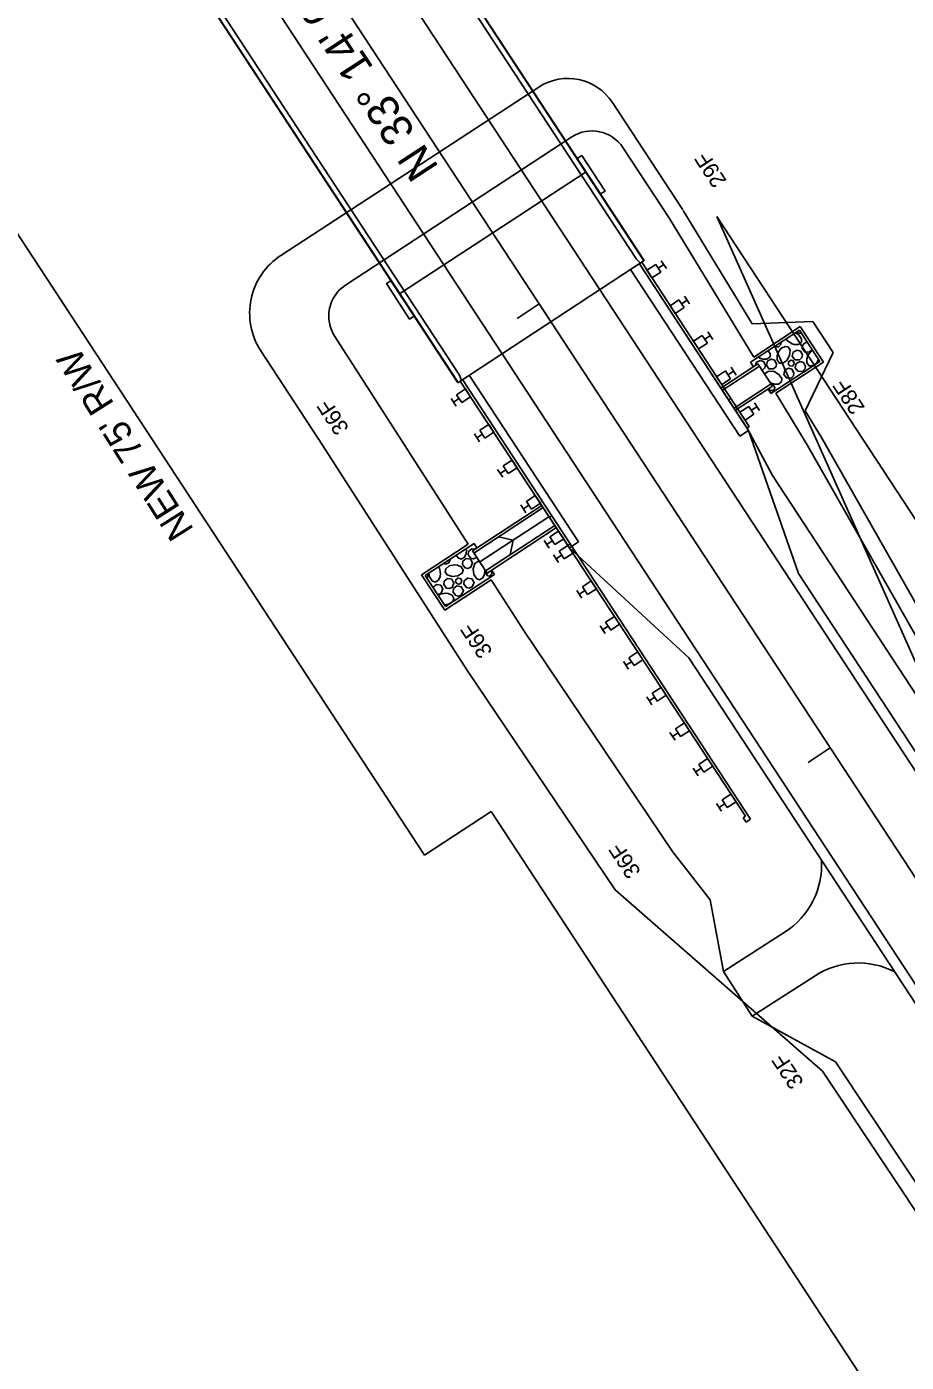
# Model space of a CAD drawing. Extents: x 1551641 to 1624343, y 1119533 to 1136600.
# Drawn here: x 1552572.7 to 1552738.3, y 1134049.4 to 1134301 of the extents above; entities that cross this region are included whole.
import ezdxf

# ---------------------------------------------------------------- set-up
doc = ezdxf.new("R2010")
doc.units = 0
for name, color, linetype in [('Prop CMT Approach Slab', 7, 'Continuous'), ('Prop CMT Concrete Structures', 7, 'Continuous'), ('Prop CMT Guardrail Graphics', 7, 'Continuous'), ('Prop CMT Pvmt Concrete', 7, 'Continuous'), ('Prop CMT Pvmt Surface Shoulder', 7, 'Continuous'), ('RD_HC_Data', 7, 'Continuous'), ('RD_HC_Data_Tic', 7, 'Continuous'), ('RD_Sketch1', 7, 'Continuous'), ('RD_XS_Base', 7, 'Continuous'), ('RD_XS_EarthShd', 7, 'Continuous'), ('RD_XS_ExGround', 7, 'Continuous'), ('RD_XS_ExPaveRet', 7, 'Continuous'), ('RD_XS_Pave', 7, 'Continuous'), ('RD_XS_PaveShd', 7, 'Continuous'), ('RD_XS_TieSlope', 7, 'Continuous'), ('RD_XS_TX_Elev_EX', 7, 'Continuous'), ('RD_XS_TX_Slope', 7, 'Continuous'), ('Scratch_Level_0', 7, 'Continuous')]:
    doc.layers.add(name, color=color, linetype=linetype)

# ---------------------------------------------------------------- blocks, each defined once
blk = doc.blocks.new('Guardrail_MTBBC3_Transition')
at = {"layer": 'RD_XS_Base'}
for p, q in [((3.525, 3.75), (1.775, 3.75)), ((2.65, 2.5), (2.65, 3.75)), ((11.525, 3.75), (9.775, 3.75)), ((10.65, 2.5), (10.65, 3.75)), ((19.525, 3.75), (17.775, 3.75)), ((18.65, 2.5), (18.65, 3.75)), ((27.525, 3.75), (25.775, 3.75)), ((26.65, 2.5), (26.65, 3.75)), ((35.525, 3.75), (33.775, 3.75)), ((34.65, 2.5), (34.65, 3.75)), ((37, 0.5), (0, 0.5)), ((0, 0.5), (0, 0)), ((0, 0), (37, 0)), ((1.775, 0.5), (1.775, 2.5)), ((1.775, 2.5), (3.525, 2.5)), ((3.525, 0.5), (1.775, 0.5)), ((3.525, 2.5), (3.525, 0.5)), ((9.775, 0.5), (9.775, 2.5)), ((9.775, 2.5), (11.525, 2.5)), ((11.525, 0.5), (9.775, 0.5)), ((11.525, 2.5), (11.525, 0.5)), ((17.775, 0.5), (17.775, 2.5)), ((17.775, 2.5), (19.525, 2.5)), ((19.525, 0.5), (17.775, 0.5)), ((19.525, 2.5), (19.525, 0.5)), ((25.775, 0.5), (25.775, 2.5)), ((25.775, 2.5), (27.525, 2.5)), ((27.525, 0.5), (25.775, 0.5)), ((27.525, 2.5), (27.525, 0.5)), ((30.65, 0.5), (30.65, 0)), ((33.775, 0.5), (33.775, 2.5)), ((33.775, 2.5), (35.525, 2.5)), ((35.525, 0.5), (33.775, 0.5)), ((35.525, 2.5), (35.525, 0.5)), ((37, 0), (37, 0.5))]:
    blk.add_line(p, q, dxfattribs=at)

msp = doc.modelspace()

# ---------------------------------------------------------------- linework, layer by layer
at = {"layer": 'Prop CMT Approach Slab'}
for p, q in [((1552718.52, 1134243.36), (1552718.45, 1134243.29)), ((1552714.26, 1134240.68), (1552713.46, 1134240.71)), ((1552710.79, 1134238.56), (1552710.5, 1134238.77)), ((1552711.25, 1134236.3), (1552711.18, 1134236.31)), ((1552712.97, 1134233.85), (1552712.64, 1134234.09)), ((1552655.51, 1134202.33), (1552655.43, 1134202.69)), ((1552652.17, 1134200.01), (1552652.47, 1134200.75)), ((1552657.39, 1134201.01), (1552657.42, 1134201.08)), ((1552658.95, 1134198.46), (1552658.87, 1134198.86)), ((1552648.02, 1134197.17), (1552648.11, 1134197.21))]:
    msp.add_line(p, q, dxfattribs=at)
for points in [[(1552717.49, 1134243.35), (1552718.1, 1134242.99), (1552718.62, 1134242.24), (1552718.59, 1134241.61), (1552718.01, 1134241.17), (1552717.24, 1134241.17), (1552716.66, 1134241.36)], [(1552718.45, 1134243.29), (1552717.92, 1134243.31), (1552717.76, 1134243.53)], [(1552714.16, 1134239.54), (1552714.74, 1134240.37), (1552715.51, 1134240.78), (1552716.07, 1134240.68), (1552716.44, 1134240.08), (1552716.36, 1134239.07), (1552715.81, 1134238.14), (1552715.06, 1134237.62), (1552714.43, 1134237.65), (1552713.99, 1134238.23), (1552713.99, 1134239), (1552714.18, 1134239.58)], [(1552714.8, 1134241.59), (1552714.71, 1134241.13), (1552714.26, 1134240.68)], [(1552716.7, 1134241.34), (1552715.88, 1134241.92), (1552715.73, 1134242.2)], [(1552720.07, 1134239.73), (1552719.2, 1134239.76), (1552718.72, 1134240.41), (1552718.9, 1134241.19), (1552719.62, 1134241.57), (1552719.7, 1134241.55)], [(1552720.55, 1134240.26), (1552720.53, 1134240.17), (1552720.07, 1134239.73)], [(1552709.95, 1134237.21), (1552710.07, 1134237.77), (1552710.8, 1134238.14), (1552711.42, 1134237.95), (1552711.8, 1134237.26), (1552711.71, 1134236.75), (1552711.25, 1134236.3)], [(1552712.35, 1134239.98), (1552712.71, 1134239.46), (1552712.68, 1134238.83), (1552712.1, 1134238.39), (1552711.33, 1134238.39), (1552710.75, 1134238.58)], [(1552713.36, 1134236.55), (1552712.48, 1134236.58), (1552712, 1134237.23), (1552712.18, 1134238.01), (1552712.91, 1134238.39), (1552713.52, 1134238.2), (1552713.91, 1134237.5), (1552713.81, 1134236.99), (1552713.36, 1134236.55)], [(1552716.92, 1134237.09), (1552716.39, 1134237.1), (1552716.1, 1134237.49), (1552716.21, 1134237.96), (1552716.64, 1134238.19), (1552717.01, 1134238.08), (1552717.25, 1134237.66), (1552717.19, 1134237.35), (1552716.91, 1134237.09)], [(1552718.22, 1134238.25), (1552717.35, 1134238.28), (1552716.87, 1134238.93), (1552717.05, 1134239.71), (1552717.77, 1134240.09), (1552718.39, 1134239.9), (1552718.78, 1134239.21), (1552718.68, 1134238.69), (1552718.22, 1134238.25)], [(1552718.8, 1134236.08), (1552717.92, 1134236.11), (1552717.44, 1134236.75), (1552717.62, 1134237.54), (1552718.34, 1134237.92), (1552718.96, 1134237.73), (1552719.35, 1134237.03), (1552719.25, 1134236.52), (1552718.8, 1134236.08)], [(1552721.82, 1134238.32), (1552721.41, 1134237.61), (1552720.66, 1134237.1), (1552720.03, 1134237.12), (1552719.59, 1134237.7), (1552719.58, 1134238.47), (1552719.77, 1134239.05)], [(1552719.75, 1134239.01), (1552720.34, 1134239.84), (1552720.7, 1134240.03)], [(1552711.76, 1134235.42), (1552711.82, 1134235.76), (1552712.42, 1134236.14), (1552713.43, 1134236.05), (1552714.36, 1134235.51), (1552714.88, 1134234.76), (1552714.85, 1134234.13), (1552714.27, 1134233.69), (1552713.5, 1134233.68), (1552712.92, 1134233.87)], [(1552716.64, 1134234.83), (1552715.76, 1134234.86), (1552715.28, 1134235.51), (1552715.46, 1134236.29), (1552716.18, 1134236.67), (1552716.8, 1134236.48), (1552717.19, 1134235.79), (1552717.09, 1134235.27), (1552716.64, 1134234.83)], [(1552713.22, 1134232.46), (1552712.69, 1134232.48), (1552712.41, 1134232.85)], [(1552712.99, 1134233.55), (1552713.32, 1134233.45), (1552713.55, 1134233.03), (1552713.49, 1134232.72), (1552713.22, 1134232.46)], [(1552657.08, 1134202.57), (1552656.52, 1134202.68), (1552655.89, 1134202.16), (1552655.81, 1134201.52), (1552656.3, 1134200.89), (1552656.8, 1134200.77), (1552657.39, 1134201.01)], [(1552651.13, 1134199.87), (1552651.59, 1134199.77), (1552652.17, 1134200.01)], [(1552653.58, 1134201.48), (1552653.92, 1134200.94), (1552654.5, 1134200.71), (1552655.13, 1134201.07), (1552655.45, 1134201.77), (1552655.51, 1134202.38)], [(1552656.33, 1134199.18), (1552656.65, 1134199.99), (1552656.25, 1134200.69), (1552655.45, 1134200.84), (1552654.82, 1134200.33), (1552654.74, 1134199.69), (1552655.23, 1134199.05), (1552655.74, 1134198.94), (1552656.32, 1134199.18)], [(1552658, 1134200.19), (1552657.66, 1134200.27), (1552657.08, 1134199.88), (1552656.75, 1134198.91), (1552656.88, 1134197.84), (1552657.36, 1134197.07), (1552657.95, 1134196.84), (1552658.58, 1134197.2), (1552658.9, 1134197.9), (1552658.95, 1134198.51)], [(1552648.11, 1134197.21), (1552648.31, 1134197.7), (1552648.17, 1134197.93)], [(1552648.44, 1134198.11), (1552648.52, 1134197.4), (1552649.01, 1134196.63), (1552649.59, 1134196.4), (1552650.23, 1134196.76), (1552650.54, 1134197.46), (1552650.6, 1134198.07)], [(1552650.6, 1134198.02), (1552650.39, 1134199.02), (1552650.2, 1134199.26)], [(1552653.27, 1134199.64), (1552652.27, 1134199.43), (1552651.59, 1134198.9), (1552651.46, 1134198.34), (1552651.86, 1134197.76), (1552652.82, 1134197.44), (1552653.89, 1134197.56), (1552654.66, 1134198.05), (1552654.89, 1134198.63), (1552654.53, 1134199.27), (1552653.83, 1134199.58), (1552653.22, 1134199.64)], [(1552659.22, 1134198.32), (1552659.18, 1134197.98), (1552659.47, 1134197.6), (1552659.78, 1134197.53), (1552660.13, 1134197.67)], [(1552660.13, 1134197.67), (1552660.32, 1134198.16), (1552660.09, 1134198.57)], [(1552650.73, 1134194.29), (1552651.05, 1134195.11), (1552650.65, 1134195.81), (1552649.85, 1134195.96), (1552649.22, 1134195.44), (1552649.21, 1134195.36)], [(1552652.82, 1134195.4), (1552653.15, 1134196.21), (1552652.74, 1134196.91), (1552651.95, 1134197.06), (1552651.32, 1134196.55), (1552651.24, 1134195.91), (1552651.73, 1134195.27), (1552652.23, 1134195.16), (1552652.82, 1134195.4)], [(1552654.59, 1134194.01), (1552654.91, 1134194.82), (1552654.51, 1134195.52), (1552653.71, 1134195.67), (1552653.08, 1134195.16), (1552653.01, 1134194.51), (1552653.49, 1134193.88), (1552654, 1134193.77), (1552654.59, 1134194.01)], [(1552654.41, 1134196.13), (1552654.61, 1134196.62), (1552654.37, 1134197.04), (1552653.89, 1134197.13), (1552653.51, 1134196.82), (1552653.46, 1134196.44), (1552653.76, 1134196.06), (1552654.06, 1134195.99), (1552654.41, 1134196.13)], [(1552656.59, 1134195.49), (1552656.92, 1134196.3), (1552656.51, 1134197), (1552655.72, 1134197.15), (1552655.08, 1134196.64), (1552655.01, 1134196), (1552655.5, 1134195.36), (1552656, 1134195.25), (1552656.59, 1134195.49)], [(1552650.05, 1134194.07), (1552650.14, 1134194.05), (1552650.73, 1134194.29)], [(1552651.52, 1134194.3), (1552650.52, 1134194.09), (1552650.2, 1134193.84)], [(1552651.33, 1134192.13), (1552652.14, 1134192.22), (1552652.91, 1134192.71), (1552653.14, 1134193.29), (1552652.78, 1134193.93), (1552652.08, 1134194.24), (1552651.47, 1134194.3)]]:
    msp.add_lwpolyline(points, dxfattribs=at)
at = {"layer": 'Prop CMT Concrete Structures'}
for p, q in [((1552710.39, 1134237.51), (1552703.42, 1134232.94)), ((1552710.67, 1134237.09), (1552703.7, 1134232.52)), ((1552710.39, 1134237.51), (1552713.14, 1134233.32)), ((1552712.86, 1134233.74), (1552705.89, 1134229.17)), ((1552713.14, 1134233.32), (1552706.16, 1134228.76))]:
    msp.add_line(p, q, dxfattribs=at)
at = {"layer": 'Prop CMT Guardrail Graphics'}
for p, q in [((1552686.4, 1134255.26), (1552706.98, 1134223.86)), ((1552688.08, 1134256.36), (1552708.65, 1134224.96)), ((1552656.01, 1134235.35), (1552676.59, 1134203.95)), ((1552654.34, 1134234.25), (1552674.91, 1134202.85)), ((1552706.98, 1134223.86), (1552708.65, 1134224.96)), ((1552676.59, 1134203.95), (1552674.91, 1134202.85))]:
    msp.add_line(p, q, dxfattribs=at)
at = {"layer": 'Prop CMT Pvmt Concrete'}
for p, q in [((1552709.01, 1134237.8), (1552718.21, 1134243.82)), ((1552722.05, 1134237.97), (1552718.21, 1134243.82)), ((1552709.56, 1134236.96), (1552709.01, 1134237.8)), ((1552712.85, 1134231.94), (1552722.05, 1134237.97)), ((1552713.14, 1134233.32), (1552710.39, 1134237.51)), ((1552712.85, 1134231.94), (1552712.3, 1134232.78)), ((1552669.68, 1134210.83), (1552656.63, 1134202.28)), ((1552669.96, 1134210.41), (1552656.9, 1134201.86)), ((1552672.15, 1134207.07), (1552659.1, 1134198.52)), ((1552672.43, 1134206.65), (1552659.37, 1134198.1)), ((1552656.92, 1134203.66), (1552647.72, 1134197.63)), ((1552657.47, 1134202.83), (1552656.92, 1134203.66)), ((1552659.37, 1134198.1), (1552656.63, 1134202.28)), ((1552651.55, 1134191.78), (1552647.72, 1134197.63)), ((1552660.76, 1134197.81), (1552651.55, 1134191.78)), ((1552660.76, 1134197.81), (1552660.21, 1134198.64))]:
    msp.add_line(p, q, dxfattribs=at)
at = {"layer": 'Prop CMT Pvmt Surface Shoulder'}
for p, q in [((1552670.99, 1134208.7), (1552658, 1134200.19)), ((1552664.29, 1134204.31), (1552661.52, 1134204.89)), ((1552664.29, 1134204.31), (1552663.72, 1134201.54))]:
    msp.add_line(p, q, dxfattribs=at)
at = {"layer": 'RD_HC_Data_Tic'}
for p, q in [((1552669.22, 1134248.79), (1552665.04, 1134246.05)), ((1552724.03, 1134165.14), (1552719.85, 1134162.4))]:
    msp.add_line(p, q, dxfattribs=at)
at = {"layer": 'RD_Sketch1'}
for p, q in [((1552718.03, 1134198.02), (1552708.65, 1134224.96)), ((1552697.38, 1134182.1), (1552674.91, 1134202.85)), ((1552843.32, 1134006.81), (1552718.03, 1134198.02)), ((1552821.57, 1133992.56), (1552697.38, 1134182.1))]:
    msp.add_line(p, q, dxfattribs=at)
at = {"layer": 'RD_XS_Base'}
for p, q in [((1552713.11, 1134216.47), (1552708.35, 1134225.41)), ((1552748.3, 1134162.77), (1552713.11, 1134216.47)), ((1552674.62, 1134203.3), (1552672.94, 1134202.21)), ((1552674.62, 1134203.3), (1552675.04, 1134203.58)), ((1552675.58, 1134201.84), (1552674.62, 1134203.3)), ((1552708.05, 1134152.28), (1552674.62, 1134203.3)), ((1552675.04, 1134203.58), (1552709.01, 1134151.72)), ((1552672.86, 1134200.06), (1552671.9, 1134201.52)), ((1552673.42, 1134201.48), (1552672.38, 1134200.79)), ((1552672.94, 1134202.21), (1552673.9, 1134200.74)), ((1552673.9, 1134200.74), (1552675.58, 1134201.84)), ((1552679, 1134196.61), (1552677.33, 1134195.52)), ((1552677.33, 1134195.52), (1552678.29, 1134194.05)), ((1552678.29, 1134194.05), (1552679.96, 1134195.15)), ((1552679.96, 1134195.15), (1552679, 1134196.61)), ((1552677.24, 1134193.37), (1552676.28, 1134194.83)), ((1552677.81, 1134194.79), (1552676.76, 1134194.1)), ((1552683.39, 1134189.92), (1552681.71, 1134188.83)), ((1552684.35, 1134188.46), (1552683.39, 1134189.92)), ((1552681.63, 1134186.68), (1552680.67, 1134188.14)), ((1552682.19, 1134188.09), (1552681.15, 1134187.41)), ((1552681.71, 1134188.83), (1552682.67, 1134187.36)), ((1552682.67, 1134187.36), (1552684.35, 1134188.46)), ((1552687.77, 1134183.23), (1552686.1, 1134182.13)), ((1552688.73, 1134181.77), (1552687.77, 1134183.23)), ((1552686.01, 1134179.99), (1552685.05, 1134181.45)), ((1552686.58, 1134181.4), (1552685.53, 1134180.72)), ((1552686.1, 1134182.13), (1552687.06, 1134180.67)), ((1552687.06, 1134180.67), (1552688.73, 1134181.77)), ((1552690.4, 1134173.29), (1552689.44, 1134174.76)), ((1552692.16, 1134176.54), (1552690.48, 1134175.44)), ((1552690.48, 1134175.44), (1552691.44, 1134173.98)), ((1552691.44, 1134173.98), (1552693.11, 1134175.07)), ((1552693.11, 1134175.07), (1552692.16, 1134176.54)), ((1552690.96, 1134174.71), (1552689.92, 1134174.03)), ((1552696.54, 1134169.85), (1552694.87, 1134168.75)), ((1552697.5, 1134168.38), (1552696.54, 1134169.85)), ((1552694.78, 1134166.6), (1552693.82, 1134168.07)), ((1552695.35, 1134168.02), (1552694.3, 1134167.33)), ((1552694.87, 1134168.75), (1552695.83, 1134167.29)), ((1552695.83, 1134167.29), (1552697.5, 1134168.38)), ((1552700.92, 1134163.16), (1552699.25, 1134162.06)), ((1552701.88, 1134161.69), (1552700.92, 1134163.16)), ((1552699.16, 1134159.91), (1552698.21, 1134161.37)), ((1552699.73, 1134161.33), (1552698.69, 1134160.64)), ((1552699.25, 1134162.06), (1552700.21, 1134160.6)), ((1552700.21, 1134160.6), (1552701.88, 1134161.69)), ((1552703.55, 1134153.22), (1552702.59, 1134154.68)), ((1552704.12, 1134154.64), (1552703.07, 1134153.95)), ((1552705.31, 1134156.46), (1552703.64, 1134155.37)), ((1552703.64, 1134155.37), (1552704.59, 1134153.9)), ((1552704.59, 1134153.9), (1552706.27, 1134155)), ((1552706.27, 1134155), (1552705.31, 1134156.46)), ((1552707.63, 1134152.01), (1552708.05, 1134152.28)), ((1552708.18, 1134151.17), (1552707.63, 1134152.01)), ((1552709.01, 1134151.72), (1552708.18, 1134151.17))]:
    msp.add_line(p, q, dxfattribs=at)
at = {"layer": 'RD_XS_EarthShd'}
for p, q in [((1552841.65, 1134005.71), (1552481.59, 1134555.23)), ((1552823.24, 1133993.65), (1552463.19, 1134543.17))]:
    msp.add_line(p, q, dxfattribs=at)
at = {"layer": 'RD_XS_ExGround'}
for p, q in [((1552688.91, 1134256.91), (1552612.18, 1134374.01)), ((1552688.98, 1134256.95), (1552612.25, 1134374.05)), ((1552653.85, 1134233.93), (1552577.12, 1134351.04)), ((1552653.92, 1134233.98), (1552577.19, 1134351.08)), ((1552678.02, 1134273.68), (1552642.89, 1134250.66)), ((1552688.98, 1134256.95), (1552653.85, 1134233.93))]:
    msp.add_line(p, q, dxfattribs=at)
for points in [[(1552688.28, 1134256.49), (1552687.53, 1134257.19), (1552611.9, 1134372.62), (1552611.56, 1134373.6)], [(1552654.55, 1134234.39), (1552654.21, 1134235.36), (1552578.58, 1134350.79), (1552577.82, 1134351.49)]]:
    msp.add_lwpolyline(points, dxfattribs=at)
for points in [[(1552680.76, 1134269.5), (1552676.38, 1134276.19), (1552677.21, 1134276.74), (1552681.6, 1134270.05)], [(1552645.63, 1134246.48), (1552641.25, 1134253.17), (1552640.41, 1134252.62), (1552644.79, 1134245.93)]]:
    msp.add_lwpolyline(points, close=True, dxfattribs=at)
at = {"layer": 'RD_XS_ExPaveRet'}
for p, q in [((1552669.15, 1134289.64), (1552620.56, 1134257.94)), ((1552696.25, 1134266.5), (1552682.98, 1134286.75)), ((1552709.33, 1134245.03), (1552696.3, 1134266.41)), ((1552720.72, 1134245.47), (1552709.33, 1134245.03)), ((1552724.56, 1134239.61), (1552720.72, 1134245.47)), ((1552628.41, 1134222.19), (1552616.79, 1134239.93)), ((1552724.56, 1134239.61), (1552719.29, 1134228.68)), ((1552722.35, 1134223.65), (1552719.29, 1134228.68)), ((1552747.11, 1134180.04), (1552722.35, 1134223.65)), ((1552655.59, 1134179.88), (1552628.41, 1134222.19)), ((1552683.53, 1134138.41), (1552655.59, 1134179.88)), ((1552722.56, 1134104.25), (1552683.53, 1134138.41)), ((1552750.16, 1134062.69), (1552722.56, 1134104.25))]:
    msp.add_line(p, q, dxfattribs=at)
for centre, radius, start, end in [((1552674.62, 1134281.27), 10, 33.2337, 123.1181), ((1552627.66, 1134247.05), 13, 123.1181, 213.2354)]:
    msp.add_arc(centre, radius, start, end, dxfattribs=at)
at = {"layer": 'RD_XS_Pave'}
for p, q in [((1552647.6, 1134144.95), (1552409.65, 1134508.1)), ((1552660.14, 1134153.17), (1552647.6, 1134144.95)), ((1552782.26, 1133966.8), (1552660.14, 1134153.17))]:
    msp.add_line(p, q, dxfattribs=at)
at = {"layer": 'RD_XS_PaveShd'}
for p, q in [((1552715.52, 1134130.49), (1552703.91, 1134123.01)), ((1552709.32, 1134114.6), (1552703.91, 1134123.01)), ((1552721.19, 1134122.25), (1552709.32, 1134114.6))]:
    msp.add_line(p, q, dxfattribs=at)
for centre, start, end in [((1552707.39, 1134143.1), 302.8006, 3.3073), ((1552729.31, 1134109.64), 63.1602, 122.8006)]:
    msp.add_arc(centre, 15, start, end, dxfattribs=at)
at = {"layer": 'RD_XS_TieSlope'}
for p, q in [((1552702.65, 1134265.28), (1552790.34, 1134131.45)), ((1552768.59, 1134117.2), (1552702.65, 1134265.28))]:
    msp.add_line(p, q, dxfattribs=at)
at = {"layer": 'RD_XS_TX_Elev_EX'}
for p, q in [((1552675.32, 1134280.25), (1552632.71, 1134252.33)), ((1552693.74, 1134264.85), (1552684.97, 1134278.23)), ((1552709.61, 1134238.79), (1552693.74, 1134264.85)), ((1552718.36, 1134244.52), (1552709.61, 1134238.79)), ((1552722.74, 1134237.82), (1552718.36, 1134244.52)), ((1552655.83, 1134203.55), (1552630.7, 1134242.68)), ((1552713.78, 1134231.95), (1552722.74, 1134237.82)), ((1552719.76, 1134222.13), (1552713.78, 1134231.95)), ((1552744.5, 1134178.56), (1552719.76, 1134222.13)), ((1552647.03, 1134197.78), (1552655.83, 1134203.55)), ((1552651.41, 1134191.09), (1552647.03, 1134197.78)), ((1552660.16, 1134196.82), (1552651.41, 1134191.09)), ((1552666.37, 1134187.14), (1552660.16, 1134196.82)), ((1552694.31, 1134145.67), (1552666.37, 1134187.14)), ((1552701.38, 1134136.53), (1552694.31, 1134145.67)), ((1552703.91, 1134123.01), (1552701.38, 1134136.53)), ((1552709.32, 1134114.6), (1552703.91, 1134123.01)), ((1552725, 1134106), (1552709.32, 1134114.6)), ((1552752.66, 1134064.35), (1552725, 1134106))]:
    msp.add_line(p, q, dxfattribs=at)
for centre, start, end in [((1552679.14, 1134274.41), 33.2337, 123.2337), ((1552636.53, 1134246.5), 123.2337, 213.2337)]:
    msp.add_arc(centre, 6.97, start, end, dxfattribs=at)
at = {"layer": 'Scratch_Level_0'}
msp.add_line((1552832.44, 1133999.68), (1552472.39, 1134549.2), dxfattribs=at)

# ---------------------------------------------------------------- block references
at = {"layer": 'RD_XS_TX_Elev_EX', "rotation": -56.76625394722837}
msp.add_blockref('Guardrail_MTBBC3_Transition', (1552688.08, 1134256.36), dxfattribs=at)
at = {"layer": 'RD_XS_TX_Elev_EX', "yscale": -0.9999999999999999, "rotation": -56.766253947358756}
msp.add_blockref('Guardrail_MTBBC3_Transition', (1552654.76, 1134234.53), dxfattribs=at)

# ---------------------------------------------------------------- texts
at = {"layer": 'RD_HC_Data'}
msp.add_text('N 33%%d 14\' 01.5" W', height=6, rotation=123.2337, dxfattribs=at).set_placement((1552650.4, 1134274.52))
at = {"layer": 'RD_XS_Pave'}
msp.add_text("NEW 75' R/W", height=5, rotation=122.3587, dxfattribs=at).set_placement((1552604.26, 1134206.26))
at = {"layer": 'RD_XS_TX_Slope'}
for s, p in [('29F', (1552704.61, 1134271.98)), ('28F', (1552730.64, 1134229.25)), ('36F', (1552633.49, 1134225.38)), ('36F', (1552660.52, 1134183.31)), ('36F', (1552688.45, 1134141.83)), ('32F', (1552719.14, 1134102.17))]:
    msp.add_text(s, height=3, rotation=123.2337, dxfattribs=at).set_placement(p)

doc.saveas('drawing.dxf')
